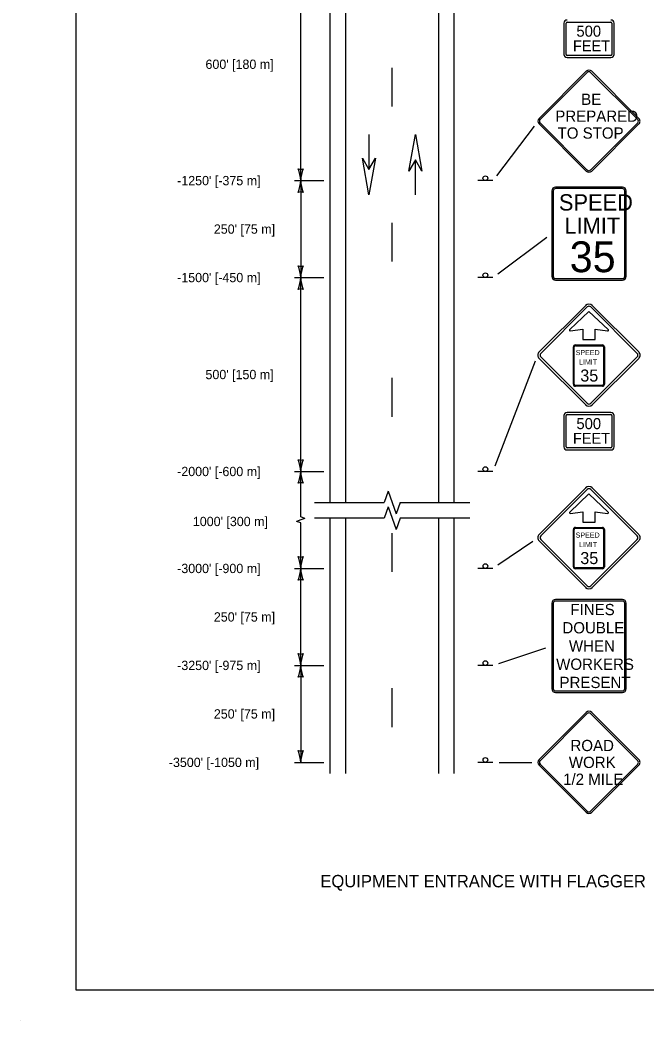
# Model space of a CAD drawing. Extents: x 49991.4 to 50021, y 49987.6 to 50011.4.
# Drawn here: x 49999.98 to 50004.02, y 49999.86 to 50006.31 of the extents above; entities that cross this region are included whole.
import ezdxf

# ---------------------------------------------------------------- set-up
doc = ezdxf.new("R2010")
doc.units = 0
for name, color, linetype in [('Level 1', 7, 'Continuous'), ('Level 2', 7, 'Continuous'), ('Level 3', 7, 'Continuous'), ('Level 6', 7, 'Continuous')]:
    doc.layers.add(name, color=color, linetype=linetype)

msp = doc.modelspace()

# ---------------------------------------------------------------- linework, layer by layer
at = {"layer": 'Level 1'}
for p, q in [((50001.9751, 50003.2038), (50001.9751, 50010.4747)), ((50002.0751, 50003.2038), (50002.0751, 50010.4747)), ((50002.6751, 50003.2038), (50002.6751, 50010.4747)), ((50002.7751, 50003.2038), (50002.7751, 50008.342)), ((50003.4814, 50006.2944), (50003.4814, 50006.0928)), ((50003.4949, 50006.0928), (50003.4949, 50006.2944)), ((50003.5016, 50006.3012), (50003.7839, 50006.3012)), ((50003.7906, 50006.2944), (50003.7906, 50006.0928)), ((50003.804, 50006.0928), (50003.804, 50006.2944)), ((50003.7839, 50006.0861), (50003.5016, 50006.0861)), ((50003.5016, 50006.0727), (50003.7839, 50006.0727)), ((50002.375, 50005.7574), (50002.375, 50006.0074)), ((50003.6251, 50005.9842), (50003.321, 50005.6802)), ((50003.6321, 50005.9772), (50003.3281, 50005.6731)), ((50003.9574, 50005.6731), (50003.6534, 50005.9772)), ((50003.9645, 50005.6802), (50003.6604, 50005.9842)), ((50003.321, 50005.6448), (50003.6251, 50005.3408)), ((50003.3281, 50005.6519), (50003.6321, 50005.3478)), ((50003.6534, 50005.3478), (50003.9574, 50005.6519)), ((50003.6604, 50005.3408), (50003.9645, 50005.6448)), ((50002.2248, 50005.5772), (50002.2248, 50005.3514)), ((50002.2251, 50005.5772), (50002.2251, 50005.3514)), ((50002.5245, 50005.187), (50002.5245, 50005.413)), ((50002.5248, 50005.187), (50002.5248, 50005.413)), ((50003.023, 50005.2795), (50002.927, 50005.2795)), ((50003.4027, 50005.2131), (50003.4027, 50004.6631)), ((50003.4127, 50005.2131), (50003.4127, 50004.6631)), ((50003.8577, 50005.2381), (50003.4277, 50005.2381)), ((50003.8577, 50005.2281), (50003.4277, 50005.2281)), ((50003.8727, 50004.6631), (50003.8727, 50005.2131)), ((50003.8827, 50004.6631), (50003.8827, 50005.2131)), ((50002.375, 50004.7574), (50002.375, 50005.0074)), ((50003.023, 50004.6545), (50002.927, 50004.6545)), ((50003.4277, 50004.6481), (50003.8577, 50004.6481)), ((50003.4277, 50004.6381), (50003.8577, 50004.6381)), ((50003.6214, 50004.4752), (50003.3221, 50004.1759)), ((50003.6315, 50004.4651), (50003.3322, 50004.1658)), ((50003.6214, 50004.4752), (50003.6214, 50004.4752)), ((50003.6315, 50004.4651), (50003.6315, 50004.4651)), ((50003.9533, 50004.1658), (50003.654, 50004.4651)), ((50003.9634, 50004.1759), (50003.6641, 50004.4752)), ((50003.6427, 50004.4367), (50003.5183, 50004.3194)), ((50003.7672, 50004.3194), (50003.6427, 50004.4367)), ((50003.5224, 50004.3108), (50003.6024, 50004.3208)), ((50003.6024, 50004.3208), (50003.6024, 50004.2553)), ((50003.6831, 50004.2553), (50003.6831, 50004.3208)), ((50003.6831, 50004.3208), (50003.7631, 50004.3108)), ((50003.6024, 50004.2553), (50003.6831, 50004.2553)), ((50003.5424, 50003.9664), (50003.5424, 50004.2077)), ((50003.5476, 50003.9664), (50003.5476, 50004.2077)), ((50003.5549, 50004.2202), (50003.7296, 50004.2202)), ((50003.5549, 50004.215), (50003.7296, 50004.215)), ((50003.6422, 50004.2202), (50003.6422, 50004.2202)), ((50003.7369, 50004.2077), (50003.7369, 50003.9664)), ((50003.7421, 50004.2077), (50003.7421, 50003.9664)), ((50003.3221, 50004.1331), (50003.6214, 50003.8338)), ((50003.3322, 50004.1432), (50003.6315, 50003.8439)), ((50003.654, 50003.8439), (50003.9533, 50004.1432)), ((50003.6641, 50003.8338), (50003.9634, 50004.1331)), ((50002.375, 50003.7574), (50002.375, 50004.0074)), ((50003.7296, 50003.9592), (50003.5549, 50003.9592)), ((50003.7296, 50003.954), (50003.5549, 50003.954)), ((50003.4814, 50003.7648), (50003.4814, 50003.5632)), ((50003.4949, 50003.5632), (50003.4949, 50003.7648)), ((50003.7839, 50003.7849), (50003.5016, 50003.7849)), ((50003.5016, 50003.7715), (50003.7839, 50003.7715)), ((50003.7906, 50003.7648), (50003.7906, 50003.5632)), ((50003.804, 50003.5632), (50003.804, 50003.7648)), ((50003.7839, 50003.5565), (50003.5016, 50003.5565)), ((50003.5016, 50003.543), (50003.7839, 50003.543)), ((50003.023, 50003.4045), (50002.927, 50003.4045)), ((50003.6214, 50003.2986), (50003.3221, 50002.9993)), ((50003.6315, 50003.2885), (50003.3322, 50002.9892)), ((50003.6214, 50003.2986), (50003.6214, 50003.2986)), ((50003.6315, 50003.2885), (50003.6315, 50003.2885)), ((50003.9533, 50002.9892), (50003.654, 50003.2885)), ((50003.9634, 50002.9993), (50003.6641, 50003.2986)), ((50003.6427, 50003.2602), (50003.5183, 50003.1429)), ((50003.7672, 50003.1429), (50003.6427, 50003.2602)), ((50001.9751, 50001.4584), (50001.9751, 50003.1038)), ((50002.0751, 50001.4584), (50002.0751, 50003.1038)), ((50002.6751, 50001.4584), (50002.6751, 50003.1038)), ((50002.7751, 50001.4584), (50002.7751, 50003.1038)), ((50003.5224, 50003.1342), (50003.6024, 50003.1443)), ((50003.6024, 50003.1443), (50003.6024, 50003.0788)), ((50003.6831, 50003.0788), (50003.6831, 50003.1443)), ((50003.6831, 50003.1443), (50003.7631, 50003.1342)), ((50003.5424, 50002.7899), (50003.5424, 50003.0312)), ((50003.5476, 50002.7899), (50003.5476, 50003.0312)), ((50003.5549, 50003.0437), (50003.7296, 50003.0437)), ((50003.5549, 50003.0385), (50003.7296, 50003.0385)), ((50003.6024, 50003.0788), (50003.6831, 50003.0788)), ((50003.6422, 50003.0437), (50003.6422, 50003.0437)), ((50003.7369, 50003.0312), (50003.7369, 50002.7899)), ((50003.7421, 50003.0312), (50003.7421, 50002.7899)), ((50002.375, 50002.7574), (50002.375, 50003.0074)), ((50003.3221, 50002.9566), (50003.6214, 50002.6573)), ((50003.3322, 50002.9667), (50003.6315, 50002.6674)), ((50003.654, 50002.6674), (50003.9533, 50002.9667)), ((50003.6641, 50002.6573), (50003.9634, 50002.9566)), ((50003.0231, 50002.7794), (50002.9271, 50002.7794)), ((50003.7296, 50002.7826), (50003.5549, 50002.7826)), ((50003.7296, 50002.7774), (50003.5549, 50002.7774)), ((50003.8577, 50002.5796), (50003.4277, 50002.5796)), ((50003.8577, 50002.5696), (50003.4277, 50002.5696)), ((50003.4027, 50002.5546), (50003.4027, 50002.0046)), ((50003.4127, 50002.5546), (50003.4127, 50002.0046)), ((50003.8727, 50002.0046), (50003.8727, 50002.5546)), ((50003.8827, 50002.0046), (50003.8827, 50002.5546)), ((50003.0231, 50002.1544), (50002.9271, 50002.1544)), ((50002.375, 50001.7574), (50002.375, 50002.0074)), ((50003.4277, 50001.9896), (50003.8577, 50001.9896)), ((50003.4277, 50001.9796), (50003.8577, 50001.9796)), ((50003.6251, 50001.8511), (50003.321, 50001.5471)), ((50003.6321, 50001.8441), (50003.3281, 50001.54)), ((50003.9574, 50001.54), (50003.6534, 50001.8441)), ((50003.9645, 50001.5471), (50003.6604, 50001.8511)), ((50003.0231, 50001.5294), (50002.9271, 50001.5294)), ((50003.321, 50001.5117), (50003.6251, 50001.2077)), ((50003.3281, 50001.5188), (50003.6321, 50001.2147)), ((50003.6534, 50001.2147), (50003.9574, 50001.5188)), ((50003.6604, 50001.2077), (50003.9645, 50001.5117)), ((49999.9766, 49999.8624), (49999.9766, 49999.8624))]:
    msp.add_line(p, q, dxfattribs=at)
for points in [[(50008.6146, 50011.2628), (50000.3356, 50011.2628), (50000.3356, 50000.0624), (50008.6146, 50000.0624)], [(50002.4828, 50005.3406), (50002.5245, 50005.5772), (50002.5664, 50005.3406), (50002.5245, 50005.4128)], [(50002.2668, 50005.4236), (50002.2251, 50005.1872), (50002.1832, 50005.4236), (50002.2251, 50005.3514)]]:
    msp.add_lwpolyline(points, close=True, dxfattribs=at)
for centre in [(50002.975, 50005.2948), (50002.975, 50004.6698), (50002.975, 50003.4198), (50002.9751, 50002.7947), (50002.9751, 50002.1697), (50002.9751, 50001.5447)]:
    msp.add_circle(centre, 0.0152, dxfattribs=at)
for centre, radius, start, end in [((50003.5016, 50006.2944), 0.0202, 90, 180), ((50003.7839, 50006.2944), 0.0202, 0, 90), ((50003.5016, 50006.2944), 0.00672, 90, 180), ((50003.7839, 50006.2944), 0.00672, 0, 90), ((50003.5016, 50006.0928), 0.0202, 180, 270), ((50003.5016, 50006.0928), 0.00672, 180, 270), ((50003.7839, 50006.0928), 0.00672, 270, 360), ((50003.7839, 50006.0928), 0.0202, 270, 360), ((50003.6427, 50005.9666), 0.025, 45, 135), ((50003.6427, 50005.9666), 0.015, 45, 135), ((50003.3387, 50005.6625), 0.025, 135, 225), ((50003.3387, 50005.6625), 0.015, 135, 225), ((50003.9468, 50005.6625), 0.015, 315, 45.00024), ((50003.9468, 50005.6625), 0.025, 315, 45.00024), ((50003.6427, 50005.3585), 0.015, 225, 314.99957), ((50003.6427, 50005.3585), 0.025, 225, 314.99957), ((50003.4278, 50005.213), 0.025, 90, 180), ((50003.4278, 50005.213), 0.015, 90, 180), ((50003.8578, 50005.213), 0.025, 0, 90), ((50003.8578, 50005.213), 0.015, 0, 90), ((50003.4278, 50004.663), 0.025, 180, 270), ((50003.4278, 50004.663), 0.015, 180, 270), ((50003.8578, 50004.663), 0.025, 270, 0), ((50003.8578, 50004.663), 0.015, 270, 0), ((50003.6427, 50004.4538), 0.0302, 45.00007, 134.99993), ((50003.6427, 50004.4538), 0.016, 45.00007, 134.99993), ((50003.5219, 50004.3158), 0.00508, 134.62874, 275.82948), ((50003.7636, 50004.3158), 0.00509, 264.38259, 45.16491), ((50003.5549, 50004.2077), 0.0125, 90, 180), ((50003.5549, 50004.2077), 0.00728, 90, 180), ((50003.7296, 50004.2077), 0.0125, 360, 90), ((50003.7296, 50004.2077), 0.00728, 360, 90), ((50003.3434, 50004.1545), 0.0302, 134.99993, 225.00008), ((50003.3434, 50004.1545), 0.016, 134.99993, 225.00008), ((50003.942, 50004.1545), 0.016, 314.99993, 45.00007), ((50003.942, 50004.1545), 0.0302, 314.99993, 45.00008), ((50003.5549, 50003.9664), 0.0125, 180, 270), ((50003.5549, 50003.9664), 0.00728, 180, 270), ((50003.7296, 50003.9664), 0.00728, 270, 360), ((50003.7296, 50003.9664), 0.0125, 270, 360), ((50003.6427, 50003.8552), 0.0302, 225.00007, 314.99993), ((50003.6427, 50003.8552), 0.016, 225.00007, 314.99993), ((50003.5016, 50003.7648), 0.0202, 90, 180), ((50003.5016, 50003.7648), 0.00672, 90, 180), ((50003.7839, 50003.7648), 0.0202, 0, 90), ((50003.7839, 50003.7648), 0.00672, 0, 90), ((50003.5016, 50003.5632), 0.0202, 180, 270), ((50003.5016, 50003.5632), 0.00672, 180, 270), ((50003.7839, 50003.5632), 0.00672, 270, 360), ((50003.7839, 50003.5632), 0.0202, 270, 360), ((50003.6427, 50003.2772), 0.0302, 45.00007, 134.99993), ((50003.6427, 50003.2772), 0.016, 45.00007, 134.99993), ((50003.5219, 50003.1393), 0.00508, 134.62874, 275.82948), ((50003.7636, 50003.1393), 0.00509, 264.38259, 45.16491), ((50003.5549, 50003.0312), 0.0125, 90, 180), ((50003.5549, 50003.0312), 0.00728, 90, 180), ((50003.7296, 50003.0312), 0.0125, 360, 90), ((50003.7296, 50003.0312), 0.00728, 360, 90), ((50003.3434, 50002.9779), 0.0302, 134.99993, 225.00008), ((50003.3434, 50002.9779), 0.016, 134.99993, 225.00008), ((50003.942, 50002.9779), 0.016, 314.99993, 45.00007), ((50003.942, 50002.9779), 0.0302, 314.99993, 45.00008), ((50003.5549, 50002.7899), 0.0125, 180, 270), ((50003.5549, 50002.7899), 0.00728, 180, 270), ((50003.7296, 50002.7899), 0.00728, 270, 360), ((50003.7296, 50002.7899), 0.0125, 270, 360), ((50003.6427, 50002.6786), 0.0302, 225.00007, 314.99993), ((50003.6427, 50002.6786), 0.016, 225.00007, 314.99993), ((50003.4278, 50002.5546), 0.025, 90, 180), ((50003.4278, 50002.5546), 0.015, 90, 180), ((50003.8578, 50002.5546), 0.025, 0, 90), ((50003.8578, 50002.5546), 0.015, 0, 90), ((50003.4278, 50002.0046), 0.025, 180, 270), ((50003.4278, 50002.0046), 0.015, 180, 270), ((50003.8578, 50002.0046), 0.025, 270, 0), ((50003.8578, 50002.0046), 0.015, 270, 0), ((50003.6427, 50001.8334), 0.025, 45, 135), ((50003.6427, 50001.8334), 0.015, 45, 135), ((50003.3387, 50001.5294), 0.025, 135, 225), ((50003.3387, 50001.5294), 0.015, 135, 225), ((50003.9468, 50001.5294), 0.015, 315, 45.00024), ((50003.9468, 50001.5294), 0.025, 315, 45.00024), ((50003.6427, 50001.2253), 0.015, 225, 314.99957), ((50003.6427, 50001.2253), 0.025, 225, 314.99957)]:
    msp.add_arc(centre, radius, start, end, dxfattribs=at)
at = {"layer": 'Level 3'}
for p, q in [((50001.7851, 50005.2795), (50001.7851, 50006.7795)), ((50003.2895, 50005.6307), (50003.0472, 50005.3113)), ((50001.745, 50005.2795), (50001.9351, 50005.2795)), ((50001.7851, 50005.2795), (50001.7851, 50004.6545)), ((50003.0551, 50004.6784), (50003.3707, 50004.9142)), ((50001.745, 50004.6545), (50001.9351, 50004.6545)), ((50001.7851, 50003.4045), (50001.7851, 50004.6545)), ((50003.0375, 50003.4418), (50003.2988, 50004.1172)), ((50001.745, 50003.4045), (50001.9351, 50003.4045)), ((50001.7851, 50003.1113), (50001.7851, 50003.4045)), ((50001.7851, 50003.0919), (50001.7577, 50003.0823)), ((50001.8125, 50003.1017), (50001.7851, 50003.1113)), ((50001.8125, 50003.1017), (50001.7851, 50003.0919)), ((50001.7851, 50003.0725), (50001.7577, 50003.0823)), ((50001.7851, 50002.7794), (50001.7851, 50003.0725)), ((50003.0561, 50002.802), (50003.2802, 50002.9554)), ((50001.745, 50002.7794), (50001.9351, 50002.7794)), ((50001.7851, 50002.1544), (50001.7851, 50002.7794)), ((50003.0611, 50002.1669), (50003.3647, 50002.267)), ((50001.745, 50002.1544), (50001.9351, 50002.1544)), ((50001.7851, 50002.1544), (50001.7851, 50001.5294)), ((50001.745, 50001.5294), (50001.9351, 50001.5294)), ((50003.063, 50001.5294), (50003.2737, 50001.5294))]:
    msp.add_line(p, q, dxfattribs=at)
for centre, radius, start, end in [((50001.7851, 50005.4077), 0.0548, 252.13882, 287.86118), ((50001.5524, 50005.268), 0.233, 2.82731, 22.07716), ((50002.0072, 50005.2703), 0.2223, 157.45601, 177.63952), ((50001.5629, 50005.2886), 0.2223, 337.45601, 357.63952), ((50002.0178, 50005.291), 0.233, 182.82731, 202.07716), ((50001.7851, 50005.1513), 0.0548, 72.13882, 107.86118), ((50001.7851, 50004.7827), 0.0548, 252.13882, 287.86118), ((50001.5524, 50004.643), 0.233, 2.82731, 22.07716), ((50002.0072, 50004.6453), 0.2223, 157.45601, 177.63952), ((50001.5629, 50004.6636), 0.2223, 337.45601, 357.63952), ((50002.0178, 50004.666), 0.233, 182.82731, 202.07716), ((50001.7851, 50004.5263), 0.0548, 72.13882, 107.86118), ((50001.7851, 50003.5327), 0.0548, 252.13882, 287.86118), ((50001.5524, 50003.393), 0.233, 2.82731, 22.07716), ((50002.0072, 50003.3953), 0.2223, 157.45601, 177.63952), ((50001.5629, 50003.4136), 0.2223, 337.45601, 357.63952), ((50002.0178, 50003.416), 0.233, 182.82731, 202.07716), ((50001.7851, 50003.2763), 0.0548, 72.13882, 107.86118), ((50001.7851, 50002.9076), 0.0548, 252.13882, 287.86118), ((50001.5524, 50002.7679), 0.233, 2.82731, 22.07716), ((50002.0072, 50002.7702), 0.2223, 157.45601, 177.63952), ((50001.5629, 50002.7885), 0.2223, 337.45601, 357.63952), ((50002.0178, 50002.7909), 0.233, 182.82731, 202.07716), ((50001.7851, 50002.6512), 0.0548, 72.13882, 107.86118), ((50001.7851, 50002.2826), 0.0548, 252.13882, 287.86118), ((50001.5524, 50002.1429), 0.233, 2.82731, 22.07716), ((50002.0072, 50002.1452), 0.2223, 157.45601, 177.63952), ((50001.5629, 50002.1635), 0.2223, 337.45601, 357.63952), ((50002.0178, 50002.1659), 0.233, 182.82731, 202.07716), ((50001.7851, 50002.0262), 0.0548, 72.13882, 107.86118), ((50001.7851, 50001.6576), 0.0548, 252.13882, 287.86118), ((50001.5524, 50001.5179), 0.233, 2.82731, 22.07716), ((50002.0072, 50001.5202), 0.2223, 157.45601, 177.63952)]:
    msp.add_arc(centre, radius, start, end, dxfattribs=at)
at = {"layer": 'Level 6'}
for p, q in [((50002.3491, 50003.2768), (50002.3233, 50003.2038)), ((50002.3491, 50003.2768), (50002.3751, 50003.2038)), ((50001.8751, 50003.2038), (50002.3233, 50003.2038)), ((50002.3491, 50003.1768), (50002.3233, 50003.1038)), ((50002.3491, 50003.1768), (50002.3751, 50003.1038)), ((50002.3751, 50003.2038), (50002.4009, 50003.1306)), ((50002.4269, 50003.2038), (50002.4009, 50003.1306)), ((50002.4269, 50003.2038), (50002.8751, 50003.2038)), ((50002.3233, 50003.1038), (50001.8751, 50003.1038)), ((50002.3751, 50003.1038), (50002.4009, 50003.0306)), ((50002.4269, 50003.1038), (50002.4009, 50003.0306)), ((50002.8751, 50003.1038), (50002.4269, 50003.1038))]:
    msp.add_line(p, q, dxfattribs=at)

# ---------------------------------------------------------------- texts
at = {"layer": 'Level 1'}
for s, height, p in [('500', 0.07124, (50003.5618, 50006.2071)), ('FEET', 0.06989, (50003.5395, 50006.113)), ('BE', 0.0725, (50003.5925, 50005.7673)), ('PREPARED', 0.0725, (50003.4256, 50005.6585)), ('TO STOP', 0.0725, (50003.4403, 50005.5498)), ('SPEED', 0.10512, (50003.4491, 50005.0865)), ('LIMIT', 0.10512, (50003.4845, 50004.9364)), ('35', 0.19892, (50003.5185, 50004.6891)), ('500', 0.07124, (50003.5618, 50003.6774)), ('FEET', 0.06989, (50003.5395, 50003.5833)), ('FINES', 0.0725, (50003.5231, 50002.4784)), ('DOUBLE', 0.0725, (50003.4715, 50002.3609)), ('WHEN', 0.0725, (50003.5136, 50002.2434)), ('WORKERS', 0.0725, (50003.4313, 50002.1259)), ('PRESENT', 0.0725, (50003.4528, 50002.0084)), ('ROAD', 0.0725, (50003.5234, 50001.6019)), ('WORK', 0.0725, (50003.513, 50001.4932)), ('1/2 MILE', 0.0725, (50003.4762, 50001.3844))]:
    msp.add_text(s, height=height, dxfattribs=at).set_placement(p)
for s, height, p in [('SPEED', 0.03301, (50003.5569, 50004.1545)), ('LIMIT', 0.03301, (50003.5787, 50004.0935)), ('35', 0.07775, (50003.5868, 50003.9841)), ('SPEED', 0.03301, (50003.5569, 50002.978)), ('LIMIT', 0.03301, (50003.5787, 50002.917)), ('35', 0.07775, (50003.5868, 50002.8075))]:
    msp.add_text(s, height=height, rotation=360, dxfattribs=at).set_placement(p)
at = {"layer": 'Level 2'}
for s, height, p in [("600' [180 m]", 0.06, (50001.1717, 50005.9995)), ("-1250' [-375 m]", 0.06, (50000.9892, 50005.2495)), ("250' [75 m]", 0.06, (50001.2256, 50004.937)), ("-1500' [-450 m]", 0.06, (50000.9892, 50004.6245)), ("500' [150 m]", 0.06, (50001.1717, 50003.9995)), ("-2000' [-600 m]", 0.06, (50000.9892, 50003.3745)), ("1000' [300 m]", 0.06, (50001.0904, 50003.0523)), ("-3000' [-900 m]", 0.06, (50000.9892, 50002.7494)), ("250' [75 m]", 0.06, (50001.2256, 50002.4369)), ("-3250' [-975 m]", 0.06, (50000.9892, 50002.1244)), ("250' [75 m]", 0.06, (50001.2256, 50001.8119)), ("-3500' [-1050 m]", 0.06, (50000.9354, 50001.4994)), ('EQUIPMENT ENTRANCE WITH FLAGGER', 0.08, (50001.9114, 50000.7238))]:
    msp.add_text(s, height=height, dxfattribs=at).set_placement(p)

doc.saveas('drawing.dxf')
